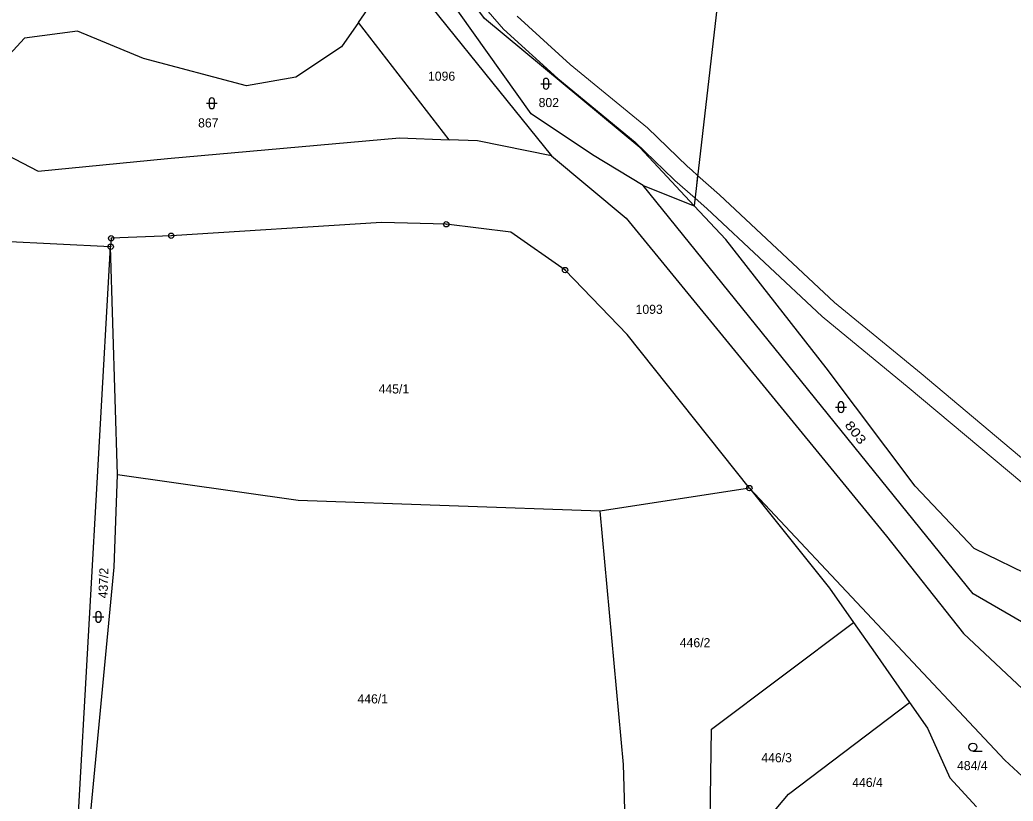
# Model space of a CAD drawing. Extents: x -758887 to -754328, y -1031688 to -1029144.
# Drawn here: x -756696 to -756511, y -1030192.8 to -1030047.3 of the extents above; entities that cross this region are included whole.
import ezdxf
from ezdxf.enums import TextEntityAlignment as Align

# ---------------------------------------------------------------- set-up
doc = ezdxf.new("R2010")
doc.units = 0
doc.header["$LTSCALE"] = 0.68
for name, color, linetype, lineweight in [('1', 7, 'Continuous', 25), ('13', 7, 'Continuous', 13), ('3', 7, 'Continuous', 25), ('8', 7, 'Continuous', 25)]:
    doc.layers.add(name, color=color, linetype=linetype, lineweight=lineweight)
doc.layers.add('2', color=7, linetype='Continuous')

msp = doc.modelspace()

# ---------------------------------------------------------------- linework, layer by layer
at = {"layer": '1'}
for p, q in [((-756553.07, -1029930.4), (-756570.42, -1030081.9)), ((-756616.02, -1030069.6), (-756632.94, -1030047.78)), ((-756579.91, -1030078.11), (-756570.42, -1030081.9)), ((-756677.83, -1030132.01), (-756679.09, -1030089.54)), ((-756560.14, -1030134.5), (-756587.94, -1030138.79))]:
    msp.add_line(p, q, dxfattribs=at)
for points in [[(-756579.91, -1030078.11), (-756589.38, -1030072.43), (-756600.79, -1030064.79), (-756622.26, -1030034.51), (-756631.29, -1030018.36), (-756653.53, -1029974.3), (-756673.49, -1029922.69), (-756670.76, -1029916.45), (-756673, -1029908.5), (-756679.01, -1029908.39)], [(-756679.01, -1029908.39), (-756674.56, -1029929.87), (-756658.58, -1029969.38), (-756628.94, -1030032.89), (-756597.01, -1030072.58)], [(-756570.42, -1030081.9), (-756580.56, -1030071.07), (-756609.47, -1030046.98), (-756619.97, -1030032.84), (-756636.3, -1030004.62), (-756646.23, -1029982.42), (-756655.17, -1029964.59), (-756664.39, -1029939.35), (-756670.76, -1029916.45)], [(-756632.94, -1030047.78), (-756630.25, -1030043.93), (-756628.94, -1030032.89)], [(-756632.94, -1030047.78), (-756636.08, -1030052.27), (-756644.58, -1030057.95), (-756653.82, -1030059.53), (-756672.95, -1030054.48), (-756685.27, -1030049.36), (-756695.13, -1030050.67), (-756701.44, -1030057.48), (-756702.14, -1030064.49), (-756698.41, -1030072.38), (-756692.57, -1030075.43), (-756668.51, -1030073.1), (-756625.31, -1030069.22), (-756616.02, -1030069.6)], [(-756597.01, -1030072.58), (-756610.78, -1030069.82), (-756616.02, -1030069.6)], [(-756597.01, -1030072.58), (-756583.11, -1030084.19), (-756534.59, -1030143.45), (-756520.23, -1030161.59), (-756491.3, -1030188.75), (-756463.64, -1030211.76), (-756441.53, -1030224.23)], [(-756487.51, -1030172.18), (-756518.44, -1030154.19), (-756579.91, -1030078.11)], [(-756483.07, -1030159.02), (-756488.45, -1030155.17), (-756506.52, -1030151.47), (-756518.3, -1030145.76), (-756529.24, -1030134.17), (-756545.86, -1030112.13), (-756564.55, -1030088.18), (-756570.42, -1030081.9)], [(-756560.14, -1030134.5), (-756582.92, -1030105.86), (-756594.47, -1030093.88), (-756604.57, -1030086.84), (-756616.59, -1030085.35), (-756628.66, -1030085.02), (-756667.82, -1030087.48), (-756679, -1030087.96), (-756679.09, -1030089.54)], [(-756685.29, -1030198.37), (-756679.09, -1030089.54), (-756699.14, -1030088.53)], [(-756683.17, -1030198.72), (-756678.44, -1030149.27), (-756677.83, -1030132.01)], [(-756587.94, -1030138.79), (-756644.18, -1030136.83), (-756677.83, -1030132.01)], [(-756505.27, -1030191.89), (-756512.58, -1030185.23), (-756560.14, -1030134.5)], [(-756560.14, -1030134.5), (-756545.19, -1030153.18), (-756540.75, -1030159.54)], [(-756582.7, -1030215.41), (-756583.57, -1030186.02), (-756587.94, -1030138.79)], [(-756567.63, -1030209.09), (-756567.19, -1030179.41), (-756540.75, -1030159.54)], [(-756540.75, -1030159.54), (-756536.73, -1030165.28), (-756530.3, -1030174.48)], [(-756567.63, -1030209.09), (-756552.82, -1030191.53), (-756530.3, -1030174.48)], [(-756530.3, -1030174.48), (-756526.96, -1030179.25), (-756522.79, -1030188.5), (-756517.86, -1030193.92)]]:
    msp.add_lwpolyline(points, dxfattribs=at)
at = {"layer": '13'}
for points in [[(-756611.63, -1030042.34), (-756605.91, -1030049.01), (-756595.8, -1030058.21), (-756581.43, -1030070.02), (-756574.19, -1030077.02), (-756574.01, -1030077.19), (-756570.26, -1030080.5), (-756569.77, -1030076.25), (-756570.86, -1030075.29), (-756571.63, -1030074.61), (-756579.09, -1030067.4), (-756593.5, -1030055.57), (-756603.39, -1030046.57)], [(-756507.1, -1030130.85), (-756528.16, -1030113.17), (-756544.29, -1030099.9), (-756565.7, -1030079.86), (-756569.77, -1030076.25), (-756570.26, -1030080.5), (-756568.06, -1030082.44), (-756546.61, -1030102.54), (-756530.4, -1030115.87), (-756509.4, -1030133.49)]]:
    msp.add_lwpolyline(points, dxfattribs=at)
at = {"layer": '3'}
for p, q in [((-756599.001, -1030059.161), (-756596.999, -1030059.161)), ((-756598.501, -1030058.661), (-756598.501, -1030059.662)), ((-756597.499, -1030059.662), (-756597.499, -1030058.661)), ((-756661.251, -1030062.801), (-756659.249, -1030062.801)), ((-756660.751, -1030062.301), (-756660.751, -1030063.302)), ((-756659.749, -1030063.302), (-756659.749, -1030062.301)), ((-756544.071, -1030119.421), (-756542.069, -1030119.421)), ((-756543.571, -1030118.921), (-756543.571, -1030119.922)), ((-756542.569, -1030119.922), (-756542.569, -1030118.921)), ((-756682.381, -1030158.501), (-756680.379, -1030158.501)), ((-756681.881, -1030158.001), (-756681.881, -1030159.002)), ((-756680.879, -1030159.002), (-756680.879, -1030158.001)), ((-756518.513, -1030183.51), (-756516.763, -1030183.51))]:
    msp.add_line(p, q, dxfattribs=at)
msp.add_circle((-756518.5129, -1030182.7598), 0.75, dxfattribs=at)
for centre, start, end in [((-756598, -1030058.6609), 0, 180), ((-756598, -1030059.6609), 180, 359.98789), ((-756660.25, -1030062.3009), 0, 180), ((-756660.25, -1030063.3009), 180, 359.98789), ((-756543.07, -1030118.9209), 0, 180), ((-756543.07, -1030119.9209), 180, 359.98789), ((-756681.38, -1030158.0009), 0, 180), ((-756681.38, -1030159.0009), 180, 359.98789)]:
    msp.add_arc(centre, 0.5, start, end, dxfattribs=at)
at = {"layer": '8'}
for centre, radius in [((-756616.59, -1030085.3499), 0.5), ((-756667.82, -1030087.4799), 0.5), ((-756616.59, -1030085.3499), 0.0303), ((-756679, -1030087.9599), 0.5), ((-756679, -1030087.9599), 0.0303), ((-756667.82, -1030087.4799), 0.0303), ((-756679.09, -1030089.5399), 0.5), ((-756679.09, -1030089.5399), 0.0303), ((-756594.47, -1030093.8799), 0.5), ((-756594.47, -1030093.8799), 0.0303), ((-756560.14, -1030134.4999), 0.5), ((-756560.14, -1030134.4999), 0.0303)]:
    msp.add_circle(centre, radius, dxfattribs=at)

# ---------------------------------------------------------------- texts
at = {"layer": '2'}
for s, p in [('1096', (-756617.46, -1030058.606)), ('802', (-756597.489, -1030063.516)), ('867', (-756660.909, -1030067.306)), ('1093', (-756578.8, -1030102.046)), ('445/1', (-756626.34, -1030116.88)), ('446/2', (-756570.25, -1030164.16)), ('446/1', (-756630.28, -1030174.63)), ('446/3', (-756555.06, -1030185.6)), ('484/4', (-756518.62, -1030187.06))]:
    msp.add_text(s, height=1.7, dxfattribs=at).set_placement(p, align=Align.CENTER)
at = {"layer": '2', "width": 1.25}
msp.add_text('803', height=1.7, rotation=308, dxfattribs=at).set_placement((-756541.0139, -1030124.6697), align=Align.CENTER)
at = {"layer": '2'}
msp.add_text('437/2', height=1.7, rotation=88, dxfattribs=at).set_placement((-756679.5895, -1030152.2297), align=Align.CENTER)
msp.add_text('446/4', height=1.7, dxfattribs=at).set_placement((-756540.98, -1030190.2))

doc.saveas('drawing.dxf')
